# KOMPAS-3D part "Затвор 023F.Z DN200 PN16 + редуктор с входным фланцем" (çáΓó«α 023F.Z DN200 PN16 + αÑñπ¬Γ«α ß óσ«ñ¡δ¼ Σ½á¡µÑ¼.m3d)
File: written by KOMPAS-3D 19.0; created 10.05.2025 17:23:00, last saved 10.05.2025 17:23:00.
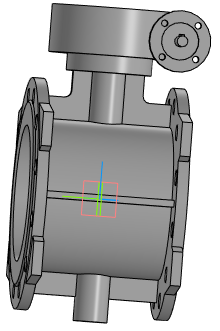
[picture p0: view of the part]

Document properties: Полное имя файла: Затвор 023F.Z DN200 PN16 + редуктор с входным фланцем.a3d

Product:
- Part/product: Затвор 023F.Z DN200 PN16 + редуктор с входным фланцем
    Масса: 59.9699

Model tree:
1. Операция без истории:1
